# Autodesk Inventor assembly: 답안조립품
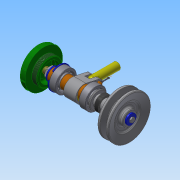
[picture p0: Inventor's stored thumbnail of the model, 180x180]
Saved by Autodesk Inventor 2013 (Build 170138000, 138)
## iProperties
Created: 2016-08
Part Number: 답안조립품
Document SubType Name: Assembly
Designer: Administrator
Author: Administrator
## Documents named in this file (25)
- C:\Users\Administrator\Desktop\460808V1020\답안조립품.iam
- C:\Users\Administrator\Desktop\460808V1020\V-벨트풀리.ipt
- C:\Users\Administrator\Desktop\460808V1020\너트 M10.ipt
- C:\Users\Administrator\Desktop\460808V1020\링크.ipt
- C:\Users\Administrator\Desktop\460808V1020\멈춤링 15 x 1.ipt
- C:\Users\Administrator\Desktop\460808V1020\멈춤링 35x1.6.ipt
- C:\Users\Administrator\Desktop\460808V1020\베어링 15 x 35 x 11.ipt
- C:\Users\Administrator\Desktop\460808V1020\본체.ipt
- C:\Users\Administrator\Desktop\460808V1020\볼트 M4 x 10.ipt
- C:\Users\Administrator\Desktop\460808V1020\볼트 M4 x 12.ipt
- C:\Users\Administrator\Desktop\460808V1020\부시1.ipt
- C:\Users\Administrator\Desktop\460808V1020\부시2.ipt
- C:\Users\Administrator\Desktop\460808V1020\분할핀 1.6 x 12.ipt
- C:\Users\Administrator\Desktop\460808V1020\사이드 커버.ipt
- 사이드 커버.ipt
- C:\Users\Administrator\Desktop\460808V1020\슬라이더.ipt
- C:\Users\Administrator\Desktop\460808V1020\오일 실 15 25 7.ipt
- C:\Users\Administrator\Desktop\460808V1020\와셔 4x16.ipt
- C:\Users\Administrator\Desktop\460808V1020\와셔 10x21.ipt
- C:\Users\Administrator\Desktop\460808V1020\클래스터 핀 6 x 24.ipt
- C:\Users\Administrator\Desktop\460808V1020\키 4 x 4 x 18.ipt
- C:\Users\Administrator\Desktop\460808V1020\탑 부시.ipt
- C:\Users\Administrator\Desktop\460808V1020\탑 커버.ipt
- 탑 커버.ipt
- C:\Users\Administrator\Desktop\460808V1020\편심축.ipt
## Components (6 placed, 3 different names)
1. V-벨트풀리:1
2. ISO 4017 M4 x 10:1
3. ISO 4762 M4 x 12:1
4. ISO 4762 M4 x 12:2
5. ISO 4762 M4 x 12:3
6. ISO 4762 M4 x 12:4
